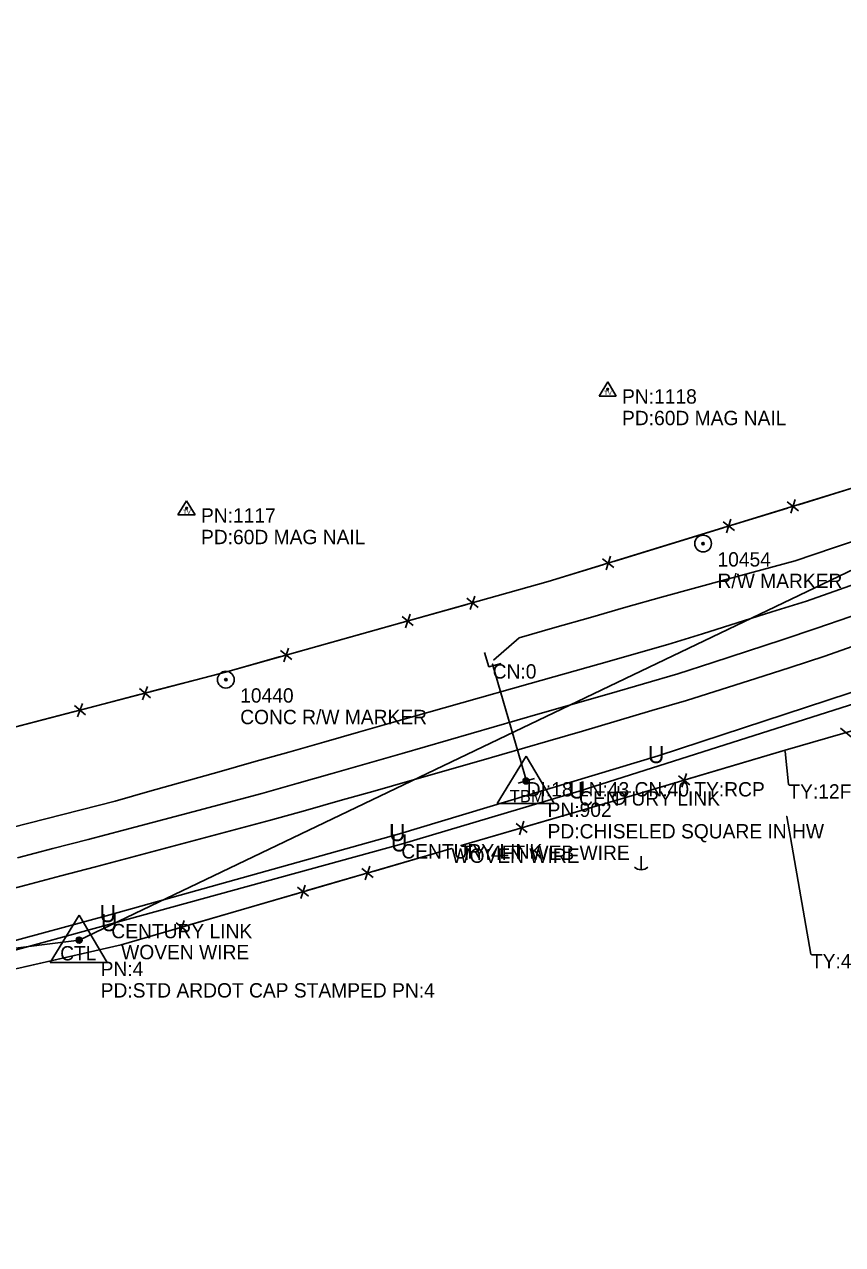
# Model space of a CAD drawing. Extents: x 1568433 to 1572450, y 731863 to 733450.
# Drawn here: x 1571298 to 1571582.8, y 732230.5 to 732655.4 of the extents above; entities that cross this region are included whole.
import ezdxf

# ---------------------------------------------------------------- set-up
doc = ezdxf.new("R2010")
doc.units = 0
for name, color, linetype in [('Default', 7, 'Continuous'), ('S_BASELINE', 7, 'Continuous'), ('S_CROSS_DRAIN', 7, 'Continuous'), ('S_CROSS_DRAIN_ANNOT', 7, 'Continuous'), ('S_DITCHLINE', 7, 'Continuous'), ('S_DRG_PT_SYM', 7, 'Continuous'), ('S_EDGE_PAVEMENT', 7, 'Continuous'), ('S_FENCE', 7, 'Continuous'), ('S_FENCE_ANNOT', 7, 'Continuous'), ('S_GATE', 7, 'Continuous'), ('S_GATE_ANNOT', 7, 'Continuous'), ('S_HEADWALL', 7, 'Continuous'), ('S_IRON_PIN', 7, 'Continuous'), ('S_IRON_PIN_ANNOT', 7, 'Continuous'), ('S_MSC_PT_SYM', 7, 'Continuous'), ('S_PAVEMENT_CROWN', 7, 'Continuous'), ('S_PRIMARY_CTL', 7, 'Continuous'), ('S_PRIMARY_CTL_ANNOT', 7, 'Continuous'), ('S_SECONDARY_CTL', 7, 'Continuous'), ('S_SECONDARY_CTL_ANNOT', 7, 'Continuous'), ('S_UNDERGROUND_CABLE', 7, 'Continuous'), ('S_UNDERGROUND_CABLE_ANNOT', 7, 'Continuous'), ('S_UTILITY_POLE', 7, 'Continuous')]:
    doc.layers.add(name, color=color, linetype=linetype)

msp = doc.modelspace()

# ---------------------------------------------------------------- linework, layer by layer
at = {"layer": 'Default'}
for points in [[(1571317.03, 732336.5), (1571317.03, 732336.55), (1571317.03, 732336.5), (1571316.98, 732336.5), (1571317.03, 732336.5), (1571317.03, 732336.45), (1571317.03, 732336.5), (1571317.08, 732336.5)], [(1571317.04, 732336.51), (1571317.04, 732336.56), (1571317.04, 732336.51), (1571316.99, 732336.51), (1571317.04, 732336.51), (1571317.04, 732336.46), (1571317.04, 732336.51), (1571317.09, 732336.51)], [(1571317.04, 732336.49), (1571317.04, 732336.54), (1571317.04, 732336.49), (1571316.99, 732336.49), (1571317.04, 732336.49), (1571317.04, 732336.44), (1571317.04, 732336.49), (1571317.09, 732336.49)]]:
    msp.add_lwpolyline(points, dxfattribs=at)
at = {"layer": 'S_BASELINE'}
for p, q in [((1571317.07, 732336.49), (1571982.53, 732655.39)), ((1570488.07, 732230.45), (1571317.07, 732336.49))]:
    msp.add_line(p, q, dxfattribs=at)
at = {"layer": 'S_CROSS_DRAIN'}
msp.add_line((1571472.84, 732391.51), (1571461, 732432.57), dxfattribs=at)
at = {"layer": 'S_DITCHLINE'}
msp.add_lwpolyline([(1571461.29, 732434), (1571470.26, 732441.76), (1571482.63, 732445.32), (1571495, 732448.87), (1571507.37, 732452.42), (1571519.74, 732455.98), (1571543.04, 732462.3), (1571566.34, 732468.63), (1571579.68, 732473.06), (1571593.02, 732477.5), (1571609.14, 732483.19), (1571625.26, 732488.88), (1571641.39, 732494.57), (1571657.51, 732500.25), (1571680.11, 732510.78), (1571702.7, 732521.31), (1571724.29, 732533.67), (1571745.87, 732546.03)], dxfattribs=at)
at = {"layer": 'S_DRG_PT_SYM'}
for points in [[(1571461, 732432.57), (1571461, 732432.62), (1571461, 732432.57), (1571460.95, 732432.57), (1571461, 732432.57), (1571461, 732432.52), (1571461, 732432.57), (1571461.05, 732432.57)], [(1571472.84, 732391.51), (1571472.84, 732391.56), (1571472.84, 732391.51), (1571472.79, 732391.51), (1571472.84, 732391.51), (1571472.84, 732391.46), (1571472.84, 732391.51), (1571472.89, 732391.51)]]:
    msp.add_lwpolyline(points, dxfattribs=at)
at = {"layer": 'S_EDGE_PAVEMENT'}
for points in [[(1571281.29, 732372.53), (1571305.48, 732378.73), (1571329.66, 732384.93), (1571341.72, 732388.33), (1571353.79, 732391.73), (1571365.85, 732395.13), (1571377.91, 732398.54), (1571390.05, 732402), (1571402.2, 732405.45), (1571414.34, 732408.91), (1571426.49, 732412.37), (1571450.27, 732419.1), (1571474.06, 732425.84), (1571498, 732432.64), (1571521.95, 732439.44), (1571534.03, 732443.21), (1571546.11, 732446.99), (1571558.19, 732450.76), (1571570.26, 732454.54), (1571593.17, 732462.65)], [(1571286.41, 732352.44), (1571298.54, 732355.64), (1571310.67, 732358.84), (1571322.8, 732362.04), (1571334.93, 732365.24), (1571347.11, 732368.49), (1571359.3, 732371.75), (1571371.49, 732375.01), (1571383.68, 732378.26), (1571395.82, 732381.68), (1571407.95, 732385.1), (1571420.08, 732388.52), (1571432.22, 732391.94), (1571456.21, 732398.85), (1571480.21, 732405.76), (1571492.28, 732409.3), (1571504.36, 732412.85), (1571516.43, 732416.4), (1571528.51, 732419.94), (1571540.52, 732423.79), (1571552.54, 732427.63), (1571564.55, 732431.48), (1571576.57, 732435.33), (1571599.95, 732443.58)]]:
    msp.add_lwpolyline(points, dxfattribs=at)
at = {"layer": 'S_FENCE'}
for p, q in [((1571480.28, 732461.34), (1571587.21, 732494.2)), ((1571564.73, 732485.15), (1571566.26, 732489.91)), ((1571564.73, 732485.15), (1571566.26, 732489.91)), ((1571563.53, 732489.07), (1571567.47, 732485.99)), ((1571563.53, 732489.07), (1571567.47, 732485.99)), ((1571541.2, 732482.21), (1571545.14, 732479.13)), ((1571541.2, 732482.21), (1571545.14, 732479.13)), ((1571542.4, 732478.29), (1571543.93, 732483.05)), ((1571542.4, 732478.29), (1571543.93, 732483.05)), ((1571499.28, 732469.32), (1571503.21, 732466.25)), ((1571499.28, 732469.32), (1571503.21, 732466.25)), ((1571500.48, 732465.41), (1571502.01, 732470.16)), ((1571500.48, 732465.41), (1571502.01, 732470.16)), ((1571367.97, 732429.81), (1571480.28, 732461.34)), ((1571453.15, 732451.6), (1571454.81, 732456.32)), ((1571453.15, 732451.6), (1571454.81, 732456.32)), ((1571452.05, 732455.54), (1571455.91, 732452.38)), ((1571452.05, 732455.54), (1571455.91, 732452.38)), ((1571429.51, 732449.22), (1571433.37, 732446.05)), ((1571429.51, 732449.22), (1571433.37, 732446.05)), ((1571430.62, 732445.27), (1571432.27, 732449.99)), ((1571430.62, 732445.27), (1571432.27, 732449.99)), ((1571387.19, 732437.34), (1571391.06, 732434.17)), ((1571387.19, 732437.34), (1571391.06, 732434.17)), ((1571388.3, 732433.4), (1571389.95, 732438.11)), ((1571388.3, 732433.4), (1571389.95, 732438.11)), ((1571253.56, 732399.93), (1571367.97, 732429.81)), ((1571338.11, 732424.13), (1571341.92, 732420.89)), ((1571338.11, 732424.13), (1571341.92, 732420.89)), ((1571339.15, 732420.17), (1571340.88, 732424.86)), ((1571339.15, 732420.17), (1571340.88, 732424.86)), ((1571315.46, 732418.22), (1571319.27, 732414.98)), ((1571315.46, 732418.22), (1571319.27, 732414.98)), ((1571316.49, 732414.25), (1571318.23, 732418.94)), ((1571316.49, 732414.25), (1571318.23, 732418.94)), ((1571562.86, 732402.61), (1571602.42, 732414.16)), ((1571582.02, 732410.34), (1571585.92, 732407.21)), ((1571582.02, 732410.34), (1571585.92, 732407.21)), ((1571506.56, 732385.9), (1571562.86, 732402.61)), ((1571525.66, 732393.7), (1571529.57, 732390.59)), ((1571525.66, 732393.7), (1571529.57, 732390.59)), ((1571526.83, 732389.78), (1571528.41, 732394.52)), ((1571526.83, 732389.78), (1571528.41, 732394.52)), ((1571450, 732369.43), (1571506.56, 732385.9)), ((1571571.75, 732331.64), (1571563.38, 732379.53)), ((1571469.15, 732377.14), (1571473.04, 732374)), ((1571469.15, 732377.14), (1571473.04, 732374)), ((1571470.29, 732373.2), (1571471.9, 732377.94)), ((1571470.29, 732373.2), (1571471.9, 732377.94)), ((1571331.7, 732334.82), (1571446.66, 732368.4)), ((1571416.67, 732357.51), (1571418.27, 732362.24)), ((1571416.67, 732357.51), (1571418.27, 732362.24)), ((1571415.52, 732361.44), (1571419.42, 732358.31)), ((1571415.52, 732361.44), (1571419.42, 732358.31)), ((1571393.05, 732354.88), (1571396.95, 732351.75)), ((1571393.05, 732354.88), (1571396.95, 732351.75)), ((1571394.2, 732350.94), (1571395.8, 732355.68)), ((1571394.2, 732350.94), (1571395.8, 732355.68)), ((1571350.85, 732342.55), (1571354.75, 732339.42)), ((1571350.85, 732342.55), (1571354.75, 732339.42)), ((1571352, 732338.62), (1571353.6, 732343.35)), ((1571352, 732338.62), (1571353.6, 732343.35)), ((1571143.4, 732291.89), (1571331.7, 732334.82))]:
    msp.add_line(p, q, dxfattribs=at)
for points in [[(1571567.4, 732488.12), (1571587.21, 732494.2)], [(1571567.4, 732488.12), (1571587.21, 732494.2)], [(1571544.54, 732481.09), (1571563.59, 732486.94)], [(1571544.54, 732481.09), (1571563.59, 732486.94)], [(1571503.15, 732468.37), (1571541.26, 732480.08)], [(1571503.15, 732468.37), (1571541.26, 732480.08)], [(1571480.28, 732461.34), (1571499.34, 732467.2)], [(1571480.28, 732461.34), (1571499.34, 732467.2)], [(1571455.9, 732454.5), (1571480.28, 732461.34)], [(1571455.9, 732454.5), (1571480.28, 732461.34)], [(1571432.82, 732448.02), (1571452.06, 732453.42)], [(1571432.82, 732448.02), (1571452.06, 732453.42)], [(1571391.05, 732436.29), (1571429.52, 732447.09)], [(1571391.05, 732436.29), (1571429.52, 732447.09)], [(1571367.97, 732429.81), (1571387.2, 732435.21)], [(1571367.97, 732429.81), (1571387.2, 732435.21)], [(1571341.95, 732423.02), (1571367.97, 732429.81)], [(1571341.95, 732423.02), (1571367.97, 732429.81)], [(1571318.75, 732416.96), (1571338.08, 732422.01)], [(1571318.75, 732416.96), (1571338.08, 732422.01)], [(1571276.76, 732405.99), (1571315.43, 732416.09)], [(1571276.76, 732405.99), (1571315.43, 732416.09)], [(1571562.86, 732402.61), (1571582.05, 732408.21)], [(1571562.86, 732402.61), (1571582.05, 732408.21)], [(1571529.53, 732392.72), (1571562.86, 732402.61)], [(1571529.53, 732392.72), (1571562.86, 732402.61)], [(1571506.56, 732385.9), (1571525.7, 732391.58)], [(1571506.56, 732385.9), (1571525.7, 732391.58)], [(1571473.02, 732376.13), (1571506.56, 732385.9)], [(1571473.02, 732376.13), (1571506.56, 732385.9)], [(1571450, 732369.43), (1571469.18, 732375.01)], [(1571450, 732369.43), (1571469.18, 732375.01)], [(1571419.39, 732360.44), (1571446.66, 732368.4)], [(1571419.39, 732360.44), (1571446.66, 732368.4)], [(1571396.37, 732353.71), (1571415.55, 732359.32)], [(1571396.37, 732353.71), (1571415.55, 732359.32)], [(1571354.71, 732341.55), (1571393.08, 732352.75)], [(1571354.71, 732341.55), (1571393.08, 732352.75)], [(1571331.7, 732334.82), (1571350.88, 732340.43)], [(1571331.7, 732334.82), (1571350.88, 732340.43)], [(1571298.08, 732327.16), (1571331.7, 732334.82)], [(1571298.08, 732327.16), (1571331.7, 732334.82)]]:
    msp.add_lwpolyline(points, dxfattribs=at)
at = {"layer": 'S_GATE'}
msp.add_line((1571563.92, 732390.77), (1571562.77, 732402.15), dxfattribs=at)
at = {"layer": 'S_HEADWALL'}
for points in [[(1571463.98, 732432.85), (1571459.67, 732431.68), (1571458.15, 732436.67)], [(1571475.52, 732392.79), (1571469.84, 732391.2)]]:
    msp.add_lwpolyline(points, dxfattribs=at)
at = {"layer": 'S_IRON_PIN'}
for centre, radius in [((1571534.25, 732474.59), 2.91), ((1571534.25, 732474.59), 0.411), ((1571534.25, 732474.59), 0.262), ((1571534.25, 732474.59), 0.212), ((1571534.25, 732474.59), 0.145), ((1571534.25, 732474.59), 0.0822), ((1571534.25, 732474.59), 0.0581), ((1571368.14, 732427.19), 2.91), ((1571368.14, 732427.19), 0.411), ((1571368.14, 732427.19), 0.262), ((1571368.14, 732427.19), 0.212), ((1571368.14, 732427.19), 0.145), ((1571368.14, 732427.19), 0.0822), ((1571368.14, 732427.19), 0.0581)]:
    msp.add_circle(centre, radius, dxfattribs=at)
at = {"layer": 'S_MSC_PT_SYM'}
for points in [[(1571480.28, 732461.34), (1571480.28, 732461.39), (1571480.28, 732461.34), (1571480.23, 732461.34), (1571480.28, 732461.34), (1571480.28, 732461.29), (1571480.28, 732461.34), (1571480.33, 732461.34)], [(1571367.97, 732429.81), (1571367.97, 732429.86), (1571367.97, 732429.81), (1571367.92, 732429.81), (1571367.97, 732429.81), (1571367.97, 732429.76), (1571367.97, 732429.81), (1571368.02, 732429.81)], [(1571562.77, 732402.15), (1571562.77, 732402.2), (1571562.77, 732402.15), (1571562.72, 732402.15), (1571562.77, 732402.15), (1571562.77, 732402.1), (1571562.77, 732402.15), (1571562.82, 732402.15)], [(1571562.86, 732402.61), (1571562.86, 732402.66), (1571562.86, 732402.61), (1571562.81, 732402.61), (1571562.86, 732402.61), (1571562.86, 732402.56), (1571562.86, 732402.61), (1571562.91, 732402.61)], [(1571563.92, 732390.77), (1571563.92, 732390.82), (1571563.92, 732390.77), (1571563.87, 732390.77), (1571563.92, 732390.77), (1571563.92, 732390.72), (1571563.92, 732390.77), (1571563.97, 732390.77)], [(1571506.56, 732385.9), (1571506.56, 732385.95), (1571506.56, 732385.9), (1571506.51, 732385.9), (1571506.56, 732385.9), (1571506.56, 732385.85), (1571506.56, 732385.9), (1571506.61, 732385.9)], [(1571563.38, 732379.53), (1571563.38, 732379.58), (1571563.38, 732379.53), (1571563.33, 732379.53), (1571563.38, 732379.53), (1571563.38, 732379.48), (1571563.38, 732379.53), (1571563.43, 732379.53)], [(1571446.66, 732368.4), (1571446.66, 732368.45), (1571446.66, 732368.4), (1571446.61, 732368.4), (1571446.66, 732368.4), (1571446.66, 732368.35), (1571446.66, 732368.4), (1571446.71, 732368.4)], [(1571450, 732369.43), (1571450, 732369.48), (1571450, 732369.43), (1571449.95, 732369.43), (1571450, 732369.43), (1571450, 732369.38), (1571450, 732369.43), (1571450.05, 732369.43)], [(1571331.7, 732334.82), (1571331.7, 732334.87), (1571331.7, 732334.82), (1571331.65, 732334.82), (1571331.7, 732334.82), (1571331.7, 732334.77), (1571331.7, 732334.82), (1571331.75, 732334.82)], [(1571571.75, 732331.64), (1571571.75, 732331.69), (1571571.75, 732331.64), (1571571.7, 732331.64), (1571571.75, 732331.64), (1571571.75, 732331.59), (1571571.75, 732331.64), (1571571.8, 732331.64)]]:
    msp.add_lwpolyline(points, dxfattribs=at)
at = {"layer": 'S_PAVEMENT_CROWN'}
msp.add_lwpolyline([(1571295.61, 732365.17), (1571307.93, 732368.35), (1571320.25, 732371.54), (1571332.57, 732374.73), (1571356.61, 732381.15), (1571380.66, 732387.57), (1571392.88, 732391.05), (1571405.11, 732394.53), (1571417.33, 732398.01), (1571429.55, 732401.48), (1571453.54, 732408.44), (1571477.54, 732415.39), (1571501.52, 732422.28), (1571525.5, 732429.17), (1571537.57, 732433.15), (1571549.64, 732437.13), (1571561.71, 732441.11), (1571573.79, 732445.09), (1571596.75, 732453.01)], dxfattribs=at)
at = {"layer": 'S_PRIMARY_CTL'}
for p, q in [((1571472.61, 732400.6), (1571462.58, 732384.09)), ((1571472.61, 732400.6), (1571462.58, 732384.09)), ((1571472.61, 732400.6), (1571482.44, 732384.09)), ((1571472.61, 732400.6), (1571482.44, 732384.09)), ((1571462.58, 732384.09), (1571482.44, 732384.09)), ((1571462.58, 732384.09), (1571482.44, 732384.09)), ((1571317.07, 732345.19), (1571307.03, 732328.68)), ((1571317.07, 732345.19), (1571307.03, 732328.68)), ((1571317.07, 732345.19), (1571326.89, 732328.68)), ((1571317.07, 732345.19), (1571326.89, 732328.68)), ((1571307.03, 732328.68), (1571326.89, 732328.68)), ((1571307.03, 732328.68), (1571326.89, 732328.68))]:
    msp.add_line(p, q, dxfattribs=at)
for centre, radius in [((1571472.61, 732391.9), 1.04), ((1571472.61, 732391.9), 1.04), ((1571472.61, 732391.9), 0.609), ((1571472.61, 732391.9), 0.609), ((1571472.61, 732391.9), 0.344), ((1571472.61, 732391.9), 0.344), ((1571317.07, 732336.49), 1.04), ((1571317.07, 732336.49), 1.04), ((1571317.07, 732336.49), 0.609), ((1571317.07, 732336.49), 0.609), ((1571317.07, 732336.49), 0.344), ((1571317.07, 732336.49), 0.344)]:
    msp.add_circle(centre, radius, dxfattribs=at)
at = {"layer": 'S_SECONDARY_CTL'}
for p, q in [((1571501.03, 732530.93), (1571498.02, 732525.97)), ((1571501.03, 732530.93), (1571503.98, 732525.97)), ((1571498.02, 732525.97), (1571503.98, 732525.97)), ((1571354.48, 732489.49), (1571351.47, 732484.54)), ((1571354.48, 732489.49), (1571357.43, 732484.54)), ((1571351.47, 732484.54), (1571357.43, 732484.54))]:
    msp.add_line(p, q, dxfattribs=at)
for centre, radius in [((1571501.03, 732528.32), 0.311), ((1571501.03, 732528.32), 0.183), ((1571501.03, 732528.32), 0.103), ((1571354.48, 732486.88), 0.311), ((1571354.48, 732486.88), 0.183), ((1571354.48, 732486.88), 0.103)]:
    msp.add_circle(centre, radius, dxfattribs=at)
at = {"layer": 'S_UNDERGROUND_CABLE'}
for p, q in [((1571518.63, 732400.68), (1571640.17, 732440.67)), ((1571491.08, 732388.34), (1571641.59, 732436.23)), ((1571428.54, 732373.52), (1571518.63, 732400.68)), ((1571429.21, 732369.91), (1571491.08, 732388.34)), ((1571327.78, 732345.29), (1571428.54, 732373.52)), ((1571328.28, 732342.13), (1571429.21, 732369.91)), ((1571231.42, 732319.3), (1571327.78, 732345.29)), ((1571232.71, 732316), (1571328.28, 732342.13))]:
    msp.add_line(p, q, dxfattribs=at)
at = {"layer": 'S_UTILITY_POLE'}
for p, q in [((1571504.78, 732388.03), (1571504.78, 732390.14)), ((1571512.63, 732365.68), (1571512.63, 732360.96))]:
    msp.add_line(p, q, dxfattribs=at)
msp.add_circle((1571504.9, 732385.89), 2.13, dxfattribs=at)
msp.add_arc((1571512.69, 732364.38), 3.41, 226.3972, 313.6028, dxfattribs=at)

# ---------------------------------------------------------------- texts
at = {"layer": 'Default'}
for p in [(1571515, 732398.13), (1571487.45, 732385.8), (1571424.91, 732370.97), (1571425.58, 732367.36), (1571324.15, 732342.75), (1571324.65, 732339.59)]:
    msp.add_text('U', height=6, dxfattribs=at).set_placement(p)
at = {"layer": 'S_CROSS_DRAIN_ANNOT'}
for s, p in [('CN:0', (1571461, 732427.57)), ('DI:18 LN:43 CN:40 TY:RCP', (1571472.84, 732386.51))]:
    msp.add_text(s, height=5, dxfattribs=at).set_placement(p)
at = {"layer": 'S_FENCE_ANNOT'}
for s, p in [('WOVEN WIRE', (1571446.66, 732363.4)), ('TY:4FT WEB WIRE', (1571450, 732364.43)), ('WOVEN WIRE', (1571331.7, 732329.82)), ('TY:4 FT WEB WIRE', (1571571.75, 732326.64))]:
    msp.add_text(s, height=5, dxfattribs=at).set_placement(p)
at = {"layer": 'S_GATE_ANNOT'}
msp.add_text('TY:12FT METAL', height=5, dxfattribs=at).set_placement((1571563.92, 732385.77))
at = {"layer": 'S_IRON_PIN_ANNOT'}
for s, p in [('10454', (1571539.25, 732466.59)), ('R/W MARKER', (1571539.25, 732459.09)), ('10440', (1571373.14, 732419.19)), ('CONC R/W MARKER', (1571373.14, 732411.69))]:
    msp.add_text(s, height=5, dxfattribs=at).set_placement(p)
at = {"layer": 'S_PRIMARY_CTL'}
for s, height, p in [('TBM', 4.287, (1571466.96, 732384.51)), ('CTL', 5, (1571310.48, 732329.42))]:
    msp.add_text(s, height=height, rotation=360, dxfattribs=at).set_placement(p)
for s, height, p in [('TBM', 4.287, (1571466.96, 732384.51)), ('CTL', 5, (1571310.48, 732329.42))]:
    msp.add_text(s, height=height, dxfattribs=at).set_placement(p)
at = {"layer": 'S_PRIMARY_CTL_ANNOT'}
for s, p in [('PN:902', (1571480.11, 732379.4)), ('PD:CHISELED SQUARE IN HW', (1571480.11, 732371.9)), ('PN:4', (1571324.57, 732323.99)), ('PD:STD ARDOT CAP STAMPED PN:4', (1571324.57, 732316.49))]:
    msp.add_text(s, height=5, dxfattribs=at).set_placement(p)
at = {"layer": 'S_SECONDARY_CTL'}
for p in [(1571499.82, 732526.31), (1571353.28, 732484.87)]:
    msp.add_text('TV', height=1.5, dxfattribs=at).set_placement(p)
at = {"layer": 'S_SECONDARY_CTL_ANNOT'}
for s, p in [('PN:1118', (1571506.03, 732523.32)), ('PD:60D MAG NAIL', (1571506.03, 732515.82)), ('PN:1117', (1571359.49, 732481.88)), ('PD:60D MAG NAIL', (1571359.49, 732474.38))]:
    msp.add_text(s, height=5, dxfattribs=at).set_placement(p)
at = {"layer": 'S_UNDERGROUND_CABLE_ANNOT'}
for p in [(1571491.08, 732383.34), (1571429.21, 732364.91), (1571328.28, 732337.13)]:
    msp.add_text('CENTURY LINK', height=5, dxfattribs=at).set_placement(p)

doc.saveas('drawing.dxf')
